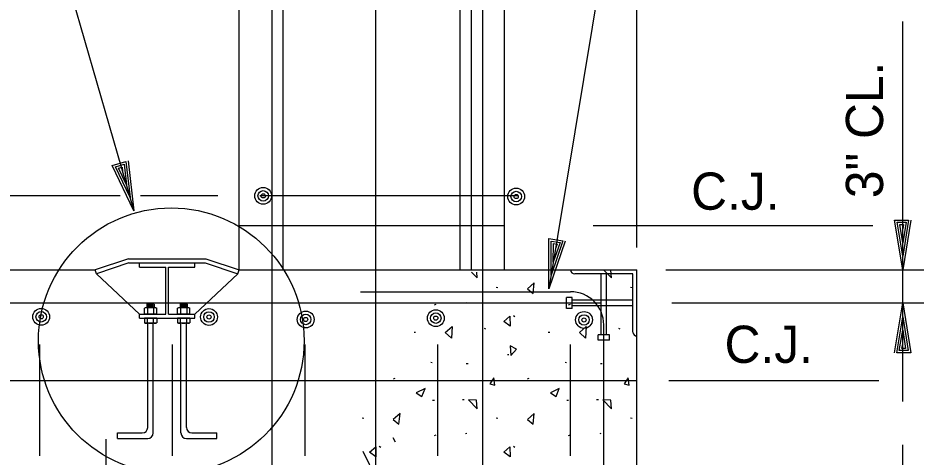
# Model space of a CAD drawing. Extents: x -11983 to -11903, y -13969.5 to -13913.5.
# Drawn here: x -11916.98 to -11910.22, y -13928.16 to -13924.86 of the extents above; entities that cross this region are included whole.
import ezdxf

# ---------------------------------------------------------------- set-up
doc = ezdxf.new("R2010")
doc.units = 0
for name, color, linetype in [('Level 2', 7, 'Continuous'), ('Level 3', 7, 'Continuous'), ('Level 44', 7, 'Continuous'), ('Level 6', 7, 'Continuous')]:
    doc.layers.add(name, color=color, linetype=linetype)

msp = doc.modelspace()

# ---------------------------------------------------------------- linework, layer by layer
at = {"layer": 'Level 2'}
for p, q in [((-11915.3142, -13926.7524), (-11915.3142, -13919.6691)), ((-11914.9812, -13926.7524), (-11914.9812, -13919.6691)), ((-11913.6492, -13926.7524), (-11913.6492, -13919.6691)), ((-11913.5642, -13926.7524), (-11913.5642, -13919.6691)), ((-11913.3162, -13926.7524), (-11913.3162, -13919.6691)), ((-11915.3142, -13926.4194), (-11913.3162, -13926.4194)), ((-11916.147, -13926.6691), (-11916.3967, -13926.7524)), ((-11916.147, -13926.6691), (-11915.5642, -13926.6691)), ((-11915.5642, -13926.6691), (-11915.3142, -13926.7524)), ((-11916.1425, -13926.7004), (-11916.387, -13926.7819)), ((-11916.1425, -13926.7004), (-11915.5687, -13926.7004)), ((-11916.0637, -13926.7316), (-11916.0637, -13926.7004)), ((-11916.0637, -13926.7316), (-11915.866, -13926.7316)), ((-11915.866, -13927.0854), (-11915.866, -13926.7316)), ((-11915.845, -13927.0854), (-11915.845, -13926.7316)), ((-11915.845, -13926.7316), (-11915.6475, -13926.7316)), ((-11915.6475, -13926.7316), (-11915.6475, -13926.7004)), ((-11915.5687, -13926.7004), (-11915.324, -13926.7819)), ((-11920.3107, -13926.7524), (-11916.3967, -13926.7524)), ((-11916.387, -13926.7819), (-11916.3967, -13926.7524)), ((-11916.0637, -13927.0854), (-11916.387, -13926.7819)), ((-11915.6475, -13927.0854), (-11915.324, -13926.7819)), ((-11915.324, -13926.7819), (-11915.3142, -13926.7524)), ((-11915.3142, -13926.7524), (-11912.3187, -13926.7524)), ((-11912.8182, -13926.7524), (-11912.8182, -13926.7524)), ((-11912.35, -13926.7836), (-11912.787, -13926.7836)), ((-11912.5892, -13927.2416), (-11912.5892, -13926.7836)), ((-11912.5477, -13927.2416), (-11912.5477, -13926.7836)), ((-11912.35, -13927.2206), (-11912.35, -13926.7836)), ((-11912.3187, -13929.5829), (-11912.3187, -13926.7524)), ((-11916.0072, -13927.0119), (-11916.0005, -13927.0051)), ((-11916.0072, -13927.0119), (-11916.0072, -13927.0376)), ((-11915.9537, -13927.0119), (-11916.0072, -13927.0119)), ((-11915.9602, -13927.0051), (-11916.0005, -13927.0051)), ((-11915.9605, -13927.0184), (-11916.0002, -13927.0184)), ((-11915.9537, -13927.0119), (-11915.9602, -13927.0051)), ((-11915.9537, -13927.0119), (-11915.9537, -13927.0376)), ((-11915.7575, -13927.0119), (-11915.7507, -13927.0051)), ((-11915.7575, -13927.0119), (-11915.7575, -13927.0376)), ((-11915.704, -13927.0119), (-11915.7575, -13927.0119)), ((-11915.7105, -13927.0051), (-11915.7507, -13927.0051)), ((-11915.7107, -13927.0184), (-11915.7505, -13927.0184)), ((-11915.704, -13927.0119), (-11915.7105, -13927.0051)), ((-11915.704, -13927.0119), (-11915.704, -13927.0376)), ((-11912.8495, -13927.0439), (-11912.8495, -13926.9606)), ((-11912.8077, -13926.9606), (-11912.8495, -13926.9606)), ((-11912.8077, -13927.0439), (-11912.8077, -13926.9606)), ((-11912.35, -13926.9814), (-11912.8077, -13926.9814)), ((-11916.0637, -13927.1166), (-11916.0637, -13927.0854)), ((-11916.0637, -13927.0854), (-11915.866, -13927.0854)), ((-11916.0205, -13927.0376), (-11916.0267, -13927.0414)), ((-11916.0267, -13927.0854), (-11916.0267, -13927.0414)), ((-11915.9342, -13927.0854), (-11916.0267, -13927.0854)), ((-11915.9402, -13927.0376), (-11916.0205, -13927.0376)), ((-11915.9537, -13927.0251), (-11916.0072, -13927.0251)), ((-11916.0072, -13927.0869), (-11916.0072, -13927.0854)), ((-11916.0037, -13927.0411), (-11916.0037, -13927.0854)), ((-11915.9605, -13927.0319), (-11916.0002, -13927.0319)), ((-11915.9575, -13927.0854), (-11915.9342, -13927.0854)), ((-11915.9572, -13927.0411), (-11915.9572, -13927.0854)), ((-11915.9537, -13927.0869), (-11915.9537, -13927.0854)), ((-11915.9402, -13927.0376), (-11915.9342, -13927.0414)), ((-11915.9342, -13927.0854), (-11915.9342, -13927.0414)), ((-11915.845, -13927.0854), (-11915.6475, -13927.0854)), ((-11915.7707, -13927.0376), (-11915.777, -13927.0414)), ((-11915.777, -13927.0854), (-11915.777, -13927.0414)), ((-11915.6845, -13927.0854), (-11915.777, -13927.0854)), ((-11915.6905, -13927.0376), (-11915.7707, -13927.0376)), ((-11915.704, -13927.0251), (-11915.7575, -13927.0251)), ((-11915.7575, -13927.0869), (-11915.7575, -13927.0854)), ((-11915.754, -13927.0411), (-11915.754, -13927.0854)), ((-11915.7107, -13927.0319), (-11915.7505, -13927.0319)), ((-11915.7077, -13927.0854), (-11915.6845, -13927.0854)), ((-11915.7075, -13927.0411), (-11915.7075, -13927.0854)), ((-11915.704, -13927.0869), (-11915.704, -13927.0854)), ((-11915.6905, -13927.0376), (-11915.6845, -13927.0414)), ((-11915.6845, -13927.0854), (-11915.6845, -13927.0414)), ((-11915.6475, -13927.1166), (-11915.6475, -13927.0854)), ((-11912.8077, -13927.0439), (-11912.8495, -13927.0439)), ((-11912.35, -13927.0229), (-11912.8077, -13927.0229)), ((-11916.0637, -13927.1166), (-11915.6475, -13927.1166)), ((-11915.9342, -13927.1166), (-11916.0267, -13927.1166)), ((-11916.0267, -13927.1166), (-11916.0267, -13927.1506)), ((-11916.0207, -13927.1541), (-11916.0267, -13927.1506)), ((-11915.9405, -13927.1541), (-11916.0207, -13927.1541)), ((-11916.0072, -13927.1149), (-11916.0072, -13927.1166)), ((-11916.0037, -13927.1506), (-11916.0037, -13927.1166)), ((-11916.0012, -13927.9389), (-11916.0012, -13927.1541)), ((-11915.9597, -13927.9804), (-11915.9597, -13927.1541)), ((-11915.9575, -13927.1166), (-11915.9342, -13927.1166)), ((-11915.9572, -13927.1506), (-11915.9572, -13927.1166)), ((-11915.9537, -13927.1149), (-11915.9537, -13927.1166)), ((-11915.9405, -13927.1541), (-11915.9342, -13927.1506)), ((-11915.9342, -13927.1166), (-11915.9342, -13927.1506)), ((-11915.6845, -13927.1166), (-11915.777, -13927.1166)), ((-11915.777, -13927.1166), (-11915.777, -13927.1506)), ((-11915.771, -13927.1541), (-11915.777, -13927.1506)), ((-11915.6907, -13927.1541), (-11915.771, -13927.1541)), ((-11915.7575, -13927.1149), (-11915.7575, -13927.1166)), ((-11915.754, -13927.1506), (-11915.754, -13927.1166)), ((-11915.7515, -13927.9804), (-11915.7515, -13927.1541)), ((-11915.71, -13927.9389), (-11915.71, -13927.1541)), ((-11915.7077, -13927.1166), (-11915.6845, -13927.1166)), ((-11915.7075, -13927.1506), (-11915.7075, -13927.1166)), ((-11915.704, -13927.1149), (-11915.704, -13927.1166)), ((-11915.6907, -13927.1541), (-11915.6845, -13927.1506)), ((-11915.6845, -13927.1166), (-11915.6845, -13927.1506)), ((-11912.5267, -13927.2416), (-11912.61, -13927.2416)), ((-11912.61, -13927.2831), (-11912.61, -13927.2416)), ((-11912.5267, -13927.2831), (-11912.61, -13927.2831)), ((-11912.5267, -13927.2831), (-11912.5267, -13927.2416)), ((-11912.3187, -13927.2519), (-11912.3187, -13927.2519)), ((-11916.8142, -13928.1529), (-11916.8142, -13927.3154)), ((-11915.8152, -13928.1529), (-11915.8152, -13927.3154)), ((-11914.8162, -13928.1529), (-11914.8162, -13927.3154)), ((-11913.8172, -13928.1529), (-11913.8172, -13927.3154)), ((-11912.8182, -13928.1529), (-11912.8182, -13927.3154)), ((-11920.3107, -13927.5849), (-11912.3187, -13927.5849)), ((-11916.2302, -13928.0219), (-11916.2302, -13927.9804)), ((-11916.2302, -13927.9804), (-11916.043, -13927.9804)), ((-11916.2302, -13928.0219), (-11916.0015, -13928.0219)), ((-11915.71, -13928.0219), (-11915.481, -13928.0219)), ((-11915.6685, -13927.9804), (-11915.481, -13927.9804)), ((-11915.481, -13928.0219), (-11915.481, -13927.9804))]:
    msp.add_line(p, q, dxfattribs=at)
for centre, radius, start, end in [((-11912.787, -13926.7524), 0.0312, 180, 270), ((-11916.0151, -13927.0578), 0.0201, 55.48902, 120.28759), ((-11915.9802, -13927.1182), 0.0805, 73.50341, 106.98163), ((-11915.9459, -13927.0578), 0.0201, 59.71241, 124.51098), ((-11915.7653, -13927.0578), 0.0201, 55.48902, 120.28759), ((-11915.7304, -13927.1182), 0.0805, 73.50341, 106.98163), ((-11915.6961, -13927.0578), 0.0201, 59.71241, 124.51098), ((-11916.0151, -13927.134), 0.0201, 239.71241, 304.51098), ((-11915.9802, -13927.0736), 0.0805, 253.01837, 286.49659), ((-11915.9459, -13927.134), 0.0201, 235.48902, 300.28759), ((-11915.7654, -13927.134), 0.0201, 239.71241, 304.51098), ((-11915.7305, -13927.0736), 0.0805, 253.01837, 286.49659), ((-11915.6961, -13927.134), 0.0201, 235.48902, 300.28759), ((-11912.3188, -13927.2206), 0.0312, 180, 270), ((-11916.0429, -13927.9387), 0.0416, 270, 0), ((-11915.6684, -13927.9387), 0.0416, 180, 270), ((-11916.0014, -13927.9802), 0.0416, 270, 0), ((-11915.7099, -13927.9802), 0.0416, 180, 270)]:
    msp.add_arc(centre, radius, start, end, dxfattribs=at)
at = {"layer": 'Level 3'}
for p, q in [((-11912.3187, -13926.5839), (-11912.3187, -13920.5411)), ((-11916.776, -13923.9909), (-11916.1055, -13926.3089)), ((-11910.3187, -13926.7524), (-11910.3187, -13924.8822)), ((-11922.6515, -13926.1932), (-11916.2094, -13926.1932)), ((-11916.0568, -13926.1932), (-11915.475, -13926.1932)), ((-11916.1345, -13926.2089), (-11916.1345, -13926.2089)), ((-11916.1055, -13926.3089), (-11916.1055, -13926.3089)), ((-11912.6473, -13926.4194), (-11910.5444, -13926.4194)), ((-11910.3187, -13927.1131), (-11910.3187, -13926.6344)), ((-11910.3187, -13926.6484), (-11910.3187, -13926.6484)), ((-11912.9652, -13926.7935), (-11912.9652, -13926.7935)), ((-11912.101, -13926.7524), (-11905.8728, -13926.7524)), ((-11910.3187, -13926.7524), (-11910.3187, -13926.7524)), ((-11912.9821, -13926.8961), (-11912.9821, -13926.8961)), ((-11912.0557, -13927.0021), (-11910.076, -13927.0021)), ((-11910.3187, -13927.7444), (-11910.3187, -13927.0021)), ((-11910.3187, -13927.0021), (-11910.3187, -13927.0021)), ((-11910.3187, -13927.1061), (-11910.3187, -13927.1061)), ((-11912.079, -13927.5849), (-11910.4984, -13927.5849)), ((-11916.3147, -13930.0624), (-11916.3147, -13928.0259)), ((-11910.3187, -13928.9169), (-11910.3187, -13928.0704)), ((-11914.383, -13928.118), (-11913.8172, -13929.2499))]:
    msp.add_line(p, q, dxfattribs=at)
for points in [[(-11912.0508, -13924.5298), (-11912.5904, -13924.5298), (-11912.9821, -13926.8961)], [(-11916.1497, -13925.9324), (-11916.1055, -13926.3089), (-11916.269, -13925.9669), (-11916.1672, -13925.9374), (-11916.1345, -13926.2089), (-11916.2452, -13925.9766), (-11916.18, -13925.9576), (-11916.1622, -13926.1129), (-11916.2217, -13925.9864), (-11916.1947, -13925.9786), (-11916.191, -13926.0131)], [(-11910.2567, -13926.3784), (-11910.3187, -13926.7524), (-11910.3807, -13926.3784), (-11910.2747, -13926.3784), (-11910.3187, -13926.6484), (-11910.3607, -13926.3944), (-11910.2927, -13926.3944), (-11910.3187, -13926.5484), (-11910.3407, -13926.4104), (-11910.3127, -13926.4104), (-11910.3187, -13926.4444)], [(-11912.8599, -13926.5373), (-11912.9821, -13926.8961), (-11912.9822, -13926.517), (-11912.8777, -13926.5344), (-11912.9652, -13926.7935), (-11912.9651, -13926.5361), (-11912.898, -13926.5472), (-11912.9488, -13926.6949), (-11912.948, -13926.5551), (-11912.9204, -13926.5597), (-11912.9318, -13926.5923)], [(-11910.3807, -13927.3761), (-11910.3187, -13927.0021), (-11910.2567, -13927.3761), (-11910.3627, -13927.3761), (-11910.3187, -13927.1061), (-11910.2767, -13927.3601), (-11910.3447, -13927.3601), (-11910.3187, -13927.2061), (-11910.2967, -13927.3441), (-11910.3247, -13927.3441), (-11910.3187, -13927.3101)]]:
    msp.add_lwpolyline(points, dxfattribs=at)
msp.add_circle((-11915.8239, -13927.2866), 1, dxfattribs=at)
msp.add_arc((-11912.8185, -13927.1671), 0.25, 0, 90, dxfattribs=at)
at = {"layer": 'Level 44'}
for p, q in [((-11913.365, -13926.887), (-11913.378, -13926.8847)), ((-11912.355, -13926.887), (-11912.368, -13926.8847)), ((-11913.8328, -13927.0137), (-11913.8463, -13927.0175)), ((-11913.5998, -13927.0002), (-11913.6095, -13927.004)), ((-11912.8228, -13927.0137), (-11912.8363, -13927.0175)), ((-11912.5898, -13927.0002), (-11912.5995, -13927.004)), ((-11913.2378, -13927.1062), (-11913.249, -13927.0995)), ((-11913.4555, -13927.1992), (-11913.4663, -13927.1942)), ((-11912.4455, -13927.1992), (-11912.4563, -13927.1942)), ((-11913.9858, -13927.2232), (-11913.9968, -13927.2242)), ((-11912.9758, -13927.2232), (-11912.9868, -13927.2242)), ((-11913.2828, -13927.3935), (-11913.2928, -13927.3927)), ((-11913.8595, -13927.452), (-11913.8695, -13927.4502)), ((-11913.5905, -13927.4605), (-11913.604, -13927.4605)), ((-11912.8495, -13927.452), (-11912.8595, -13927.4502)), ((-11912.5805, -13927.4605), (-11912.594, -13927.4605)), ((-11914.1425, -13927.5697), (-11914.1545, -13927.5757)), ((-11913.1325, -13927.5697), (-11913.1445, -13927.5757)), ((-11913.8435, -13927.7357), (-11913.857, -13927.7357)), ((-11913.6195, -13927.731), (-11913.6323, -13927.731)), ((-11912.8335, -13927.7357), (-11912.847, -13927.7357)), ((-11912.6095, -13927.731), (-11912.6223, -13927.731)), ((-11914.375, -13927.8707), (-11914.388, -13927.8685)), ((-11913.365, -13927.8707), (-11913.378, -13927.8685)), ((-11912.355, -13927.8707), (-11912.368, -13927.8685)), ((-11913.8328, -13927.9975), (-11913.8463, -13928.0012)), ((-11913.5998, -13927.984), (-11913.6095, -13927.9877)), ((-11912.8228, -13927.9975), (-11912.8363, -13928.0012)), ((-11912.5898, -13927.984), (-11912.5995, -13927.9877)), ((-11914.2478, -13928.09), (-11914.259, -13928.0832)), ((-11913.2378, -13928.09), (-11913.249, -13928.0832))]:
    msp.add_line(p, q, dxfattribs=at)
for points in [[(-11913.5635, -13926.77), (-11913.5208, -13926.8137), (-11913.5243, -13926.7694)], [(-11912.5673, -13926.7559), (-11912.5108, -13926.8137), (-11912.5154, -13926.7551)]]:
    msp.add_lwpolyline(points, dxfattribs=at)
for points in [[(-11913.092, -13926.851), (-11913.1433, -13926.8957), (-11913.1008, -13926.9315)], [(-11913.2733, -13927.177), (-11913.3213, -13927.1407), (-11913.2753, -13927.1)], [(-11913.7155, -13927.2672), (-11913.7618, -13927.2245), (-11913.7105, -13927.1787)], [(-11912.7055, -13927.2672), (-11912.7518, -13927.2245), (-11912.7005, -13927.1787)], [(-11913.2683, -13927.397), (-11913.2255, -13927.349), (-11913.2733, -13927.3235)], [(-11913.3885, -13927.6205), (-11913.3955, -13927.5657), (-11913.4263, -13927.6115)], [(-11912.3785, -13927.6205), (-11912.3855, -13927.5657), (-11912.4163, -13927.6115)], [(-11913.938, -13927.7065), (-11913.9143, -13927.6452), (-11913.9805, -13927.6775)], [(-11912.928, -13927.7065), (-11912.9043, -13927.6452), (-11912.9705, -13927.6775)], [(-11913.5258, -13927.7342), (-11913.5858, -13927.731), (-11913.5208, -13927.7975)], [(-11912.5158, -13927.7342), (-11912.5758, -13927.731), (-11912.5108, -13927.7975)], [(-11914.102, -13927.8347), (-11914.1533, -13927.8795), (-11914.1108, -13927.9152)], [(-11913.092, -13927.8347), (-11913.1433, -13927.8795), (-11913.1008, -13927.9152)], [(-11914.2833, -13928.1607), (-11914.3313, -13928.1245), (-11914.2853, -13928.0837)], [(-11913.2733, -13928.1607), (-11913.3213, -13928.1245), (-11913.2753, -13928.0837)]]:
    msp.add_lwpolyline(points, close=True, dxfattribs=at)
at = {"layer": 'Level 6'}
for p, q in [((-11915.0645, -13928.8739), (-11915.0645, -13919.9188)), ((-11914.288, -13919.9188), (-11914.288, -13928.7258)), ((-11913.4808, -13919.9188), (-11913.4808, -13928.7749)), ((-11915.1585, -13926.1918), (-11913.2113, -13926.1918)), ((-11914.401, -13926.9171), (-11912.8185, -13926.9171)), ((-11919.9924, -13927.0021), (-11912.5859, -13927.0021)), ((-11912.5685, -13928.6669), (-11912.5685, -13927.1674)), ((-11914.156, -13928.0139), (-11914.14, -13928.0459))]:
    msp.add_line(p, q, dxfattribs=at)
for centre, radius in [((-11915.1324, -13926.1957), 0.0633), ((-11913.2277, -13926.2008), 0.0633), ((-11915.1324, -13926.1957), 0.0396), ((-11915.1324, -13926.1957), 0.0158), ((-11913.2277, -13926.2008), 0.0396), ((-11913.2277, -13926.2008), 0.0158), ((-11916.8034, -13927.106), 0.0633), ((-11916.8034, -13927.106), 0.0396), ((-11915.5403, -13927.1074), 0.0633), ((-11915.5403, -13927.1074), 0.0396), ((-11914.8122, -13927.126), 0.0633), ((-11914.8122, -13927.126), 0.0396), ((-11913.8332, -13927.116), 0.0633), ((-11913.8332, -13927.116), 0.0396), ((-11912.7175, -13927.1296), 0.0633), ((-11916.8034, -13927.106), 0.0158), ((-11915.5403, -13927.1074), 0.0158), ((-11914.8122, -13927.126), 0.0158), ((-11913.8332, -13927.116), 0.0158), ((-11912.7175, -13927.1296), 0.0396), ((-11912.7175, -13927.1296), 0.0158)]:
    msp.add_circle(centre, radius, dxfattribs=at)

# ---------------------------------------------------------------- texts
at = {"layer": 'Level 3'}
msp.add_text('3" CL.', height=0.28, rotation=90, dxfattribs=at).set_placement((-11910.4663, -13926.2131))
for p in [(-11911.9112, -13926.3), (-11911.6596, -13927.4529)]:
    msp.add_text('C.J.', height=0.28, dxfattribs=at).set_placement(p)

doc.saveas('drawing.dxf')
